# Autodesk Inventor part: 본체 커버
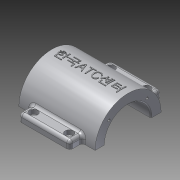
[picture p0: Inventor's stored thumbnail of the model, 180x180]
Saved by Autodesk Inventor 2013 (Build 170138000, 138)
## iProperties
Company: 한국ATC센터
Created: 2014-02
Part Number: 본체 커버
Document SubType Name: Modeling
Designer: KYOUNG IL JANG
Density: 2.71 g/cm^3
Mass: 197.605 g
Surface Area: 197.357 cm^2
Volume: 72.9171 cm^3
Material: 알루미늄-6061
Vendor: CBT Solutions
Author: KYOUNG IL JANG
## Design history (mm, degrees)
sketch "스케치1"
  geometry: L1 (-45, 40)-(45, 40); L2 (45, 40)-(45, -40); L3 (45, -40)-(-45, -40); L4 (-45, -40)-(-45, 40); 3 further points
  constraints: 8 end point, 2 midpoint, 2 parallel, 1 horizontal, 1 horizontal alignment, 1 perpendicular, 1 vertical alignment
  dimensions: "d0" = 90 distance of L2.end L3.end; "d1" = 80 distance of L1.end L2.end
extrude "돌출1" new body sketch "스케치1" distance "d2" = 10; taper "d3" = 0 deg
sketch "스케치2"
  geometry: L1 (40, 0)-(-40, 0) reference; C1 r 32.5 at (0, 80); 2 further points
  constraints: 1 centre point, 1 midpoint, 1 vertical alignment
  dimensions: "d4" = 65 diameter of C1; "d5" = 80 distance from line of C1.centre L1
extrude "돌출2" join sketch "스케치2" stored distance "d6" = 75; taper "d7" = 0 deg
sketch "스케치3"
  geometry: L1 (-7.5, -20)-(7.5, -20); L2 (7.5, 20)-(-7.5, 20); A1 r 20 centre (7.5, 0) between (7.5, -20) and (7.5, 20); A2 r 20 centre (-7.5, 0) between (-7.5, 20) and (-7.5, -20); 2 further points
  constraints: 4 end point, 4 point on circle, 4 tangent, 2 centre point, 1 horizontal, 1 horizontal alignment, 1 midpoint, 1 parallel, 1 vertical alignment
  dimensions: "d8" = 20 radius of A2; "d9" = 55 dimension on A1 A2
extrude "돌출3" join sketch "스케치3" stored distance "d10" = 75; taper "d11" = 0 deg
fillet "모깎기1" dims "d12" = 10
sketch "스케치4"
  geometry: L1 (-45, 0)-(-45, 10) reference; L2 (37.5, 47.5)-(-37.5, 47.5) reference; L3 (-45, 10)-(-27.513, 47.5); 1 further point
  constraints: 2 end point, 1 point on line
  dimensions: "d13" = 25 deg angle of L3 L1
sketch "스케치5"
  geometry: L1 (-40, 0)-(-40, 10) reference; L2 (-40, 10)-(-22.912, 56.95); 2 further points
  constraints: 2 end point, 2 other
  dimensions: "d14" = 20 deg angle of L2 L1
feature "리브1" dims "d15" = 1, "d16" = 6, "d17" = 0
feature "리브2" dims "d18" = 1, "d19" = 6, "d20" = 0
fillet "모깎기2" dims "d21" = 3
fillet "모깎기3" dims "d22" = 3
fillet "모깎기4" dims "d23" = 3
fillet "모깎기5" dims "d24" = 3
fillet "모깎기6" dims "d25" = 3
fillet "모깎기7" dims "d26" = 3
fillet "모깎기8" dims "d27" = 3
sketch "스케치6"
  geometry: A1 r 10 centre (35, -30) between (35, -40) and (45, -30) reference; 1 further point
hole "구멍1" sketch "스케치6" at (35, -30) diameter "d28" = 10; stored, may be unused: countersink angle "d32" = 90 deg, drill point angle "d34" = 118 deg; dims "d29" = 6, "d30" = 4, "d31" = 2, "d33" = 8
hole "구멍2" diameter "d37" = 45; stored, may be unused: countersink angle "d41" = 90 deg, drill point angle "d43" = 118 deg; dims "d35" = 10, "d36" = 10, "d38" = 6, "d39" = 4, "d40" = 2, "d42" = 8
sketch "스케치7"
  geometry: C1 r 22.5 at (0, 0) reference; 2 further points
  dimensions: "d44" = 135 deg dimension on C1.centre point (-18.738, 18.738) point (80, 0); "d45" = 26.5 distance of point (-18.738, 18.738) C1.centre
hole "구멍3" sketch "스케치7" at (-18.738, 18.738) diameter "d46" = 2.459; stored, may be unused: countersink angle "d50" = 90 deg, drill point angle "d52" = 118 deg; dims "d47" = 8, "d48" = 4, "d49" = 2, "d51" = 10
node "작업 평면1"
chamfer "모따기1" distance "d69" = 1; stored, may be unused: second distance "d70" = 2, angle "d71" = 45 deg
sketch "스케치9"
  geometry: L1 (-31.623, 87.5)-(-45, 87.5); L2 (-45, 87.5)-(-45, 72.5); L3 (-45, 72.5)-(-31.623, 72.5); A1 r 32.5 centre (0, 80) between (-31.623, 87.5) and (-31.623, 72.5) reference; 1 further point
  constraints: 6 end point, 2 parallel, 2 point on circle, 1 horizontal, 1 perpendicular
  dimensions: "d73" = 15 distance of L1.end L2.end; "d74" = 45 distance from line of A1.centre L2
extrude "돌출5" join sketch "스케치9" stored distance "d75" = 50; taper "d76" = 0 deg
fillet "모깎기10" dims "d77" = 3
fillet "모깎기11" dims "d78" = 3
sketch "스케치10"
  geometry: L1 (100.378, 66.389)-(0, 66.389); L2 (0, 66.389)-(0, -76.978); L3 (0, -76.978)-(100.378, -76.978); L4 (100.378, -76.978)-(100.378, 66.389); C1 r 32.5 at (0, 0) reference; 1 further point
  constraints: 8 end point, 2 parallel, 1 horizontal, 1 perpendicular, 1 point on line
extrude "돌출6" cut sketch "스케치10" stored distance "d79" = 10; taper "d80" = 0 deg
sketch "스케치11"
  geometry: C1 r 1.621 at (4.5, 4) reference; C2 r 1.621 at (39.5, 4) reference; 1 further point
hole "구멍5" sketch "스케치11" at (39.5, 4), (4.5, 4) diameter "d81" = 4.5; stored, may be unused: countersink angle "d85" = 90 deg, drill point angle "d87" = 118 deg; dims "d82" = 6, "d83" = 8, "d84" = 4.4, "d86" = 8
node "작업 평면2"
sketch "스케치12"
  geometry: 2 further points
  constraints: 1 coincident, 1 other
feature "엠보싱1" sketch "스케치12" dims "d8" = 20, "d9" = 55, "d88" = 0.5, "d89" = 0
node "솔리드1"
mirror "대칭1"
mirror "대칭2"
mirror "대칭3"
mirror "대칭4"
pattern_circular "원형 패턴1" dims angle "d54" = 360 deg
mirror "대칭5"
mirror "대칭6"
mirror "대칭7"
node "참조1"
node "참조2"
other parameters: "d56" = -117
